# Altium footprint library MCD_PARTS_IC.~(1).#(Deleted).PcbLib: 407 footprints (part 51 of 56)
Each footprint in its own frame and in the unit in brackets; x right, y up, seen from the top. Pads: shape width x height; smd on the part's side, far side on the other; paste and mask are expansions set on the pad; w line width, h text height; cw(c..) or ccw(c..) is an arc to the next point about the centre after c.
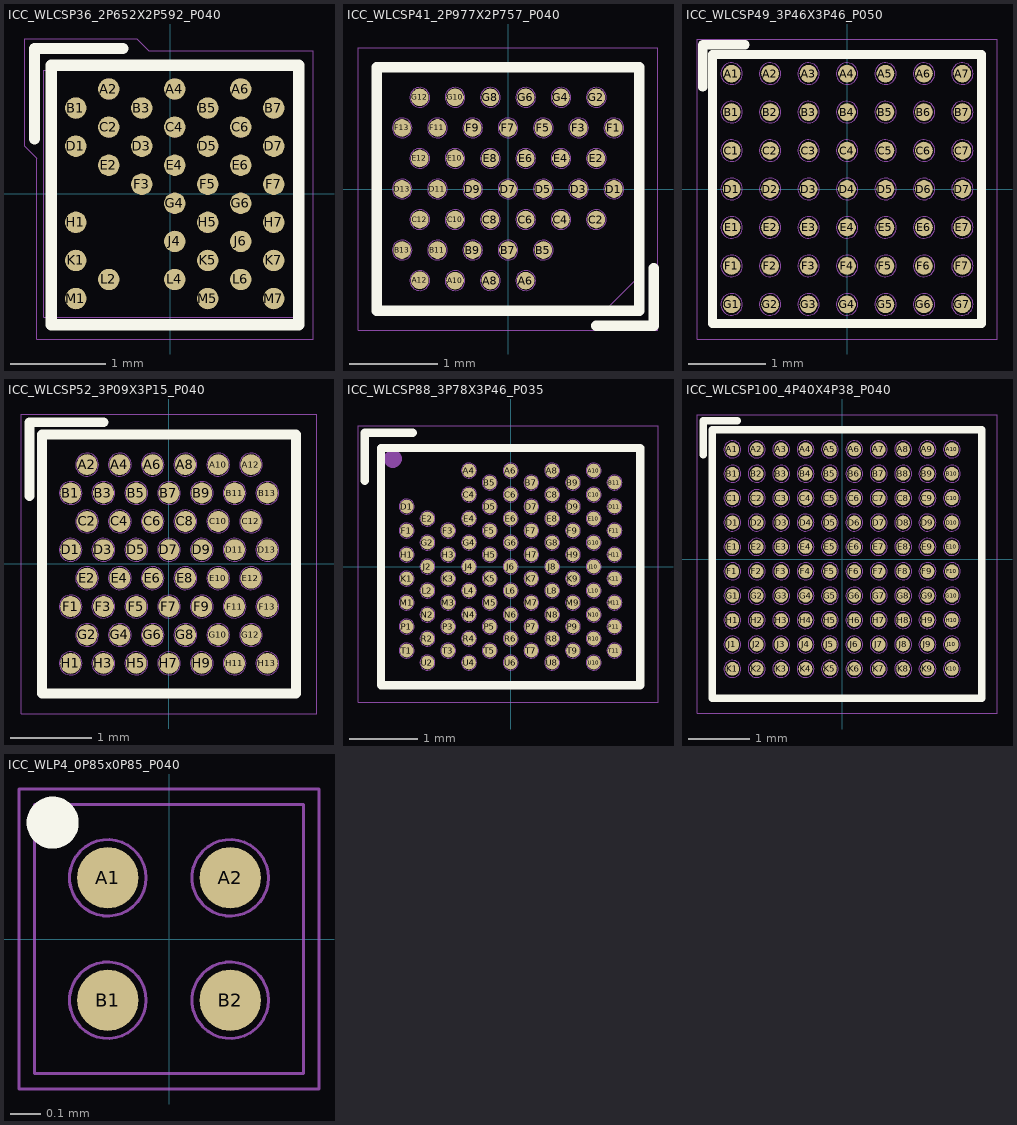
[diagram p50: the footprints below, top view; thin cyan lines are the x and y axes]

## ICC_WLCSP36_2P652X2P592_P040 [mm]
height 0.422
pads (36):
  round 0.225 smd paste+0.012 mask+0.032: A2(-0.644,1.1) A4(0.048,1.1) A6(0.741,1.1) B1(-0.991,0.9) B3(-0.298,0.9) B5(0.395,0.9) B7(1.088,0.9) C2(-0.644,0.7) C4(0.048,0.7) C6(0.741,0.7) D1(-0.991,0.5) D3(-0.298,0.5) D5(0.395,0.5) D7(1.088,0.5) E2(-0.644,0.3) E4(0.048,0.3) E6(0.741,0.3) F3(-0.298,0.1) F5(0.395,0.1) F7(1.088,0.1) G4(0.048,-0.1) G6(0.741,-0.1) H1(-0.991,-0.3) H5(0.395,-0.3) H7(1.088,-0.3) J4(0.048,-0.5) J6(0.741,-0.5) K1(-0.991,-0.7) K5(0.395,-0.7) K7(1.088,-0.7) L2(-0.644,-0.9) L4(0.048,-0.9) L6(0.741,-0.9) M1(-0.991,-1.1) M5(0.395,-1.1) M7(1.088,-1.1)
Top Overlay:
  lines w0.12: -1.425,0.575 -1.425,1.525 -0.5,1.525 ; -1.25,-1.375 1.35,-1.375 1.35,1.35 -1.25,1.35 -1.25,-1.375
M14-Top Assembly:
  circle w0.01: c-0.991,-1.1 r0.101
  circle w0.01: c0.395,-1.1 r0.101
  circle w0.01: c1.088,-1.1 r0.101
  circle w0.01: c-0.991,-0.7 r0.101
  circle w0.01: c0.395,-0.7 r0.101
  circle w0.01: c1.088,-0.7 r0.101
  circle w0.01: c-0.991,-0.3 r0.101
  circle w0.01: c0.395,-0.3 r0.101
  circle w0.01: c1.088,-0.3 r0.101
  circle w0.01: c-0.298,0.1 r0.101
  circle w0.01: c0.395,0.1 r0.101
  circle w0.01: c1.088,0.1 r0.101
  circle w0.01: c-0.991,0.5 r0.101
  circle w0.01: c-0.298,0.5 r0.101
  circle w0.01: c0.395,0.5 r0.101
  circle w0.01: c1.088,0.5 r0.101
  circle w0.01: c-0.991,0.9 r0.101
  circle w0.01: c-0.298,0.9 r0.101
  circle w0.01: c0.395,0.9 r0.101
  circle w0.01: c1.088,0.9 r0.101
  circle w0.01: c0.048,-0.1 r0.101
  circle w0.01: c0.741,-0.1 r0.101
  circle w0.01: c0.048,0.3 r0.101
  circle w0.01: c0.048,0.7 r0.101
  circle w0.01: c0.048,1.1 r0.101
  circle w0.01: c0.048,-0.5 r0.101
  circle w0.01: c0.048,-0.9 r0.101
  circle w0.01: c0.741,0.3 r0.101
  circle w0.01: c0.741,0.7 r0.101
  circle w0.01: c0.741,1.1 r0.101
  circle w0.01: c0.741,-0.5 r0.101
  circle w0.01: c0.741,-0.9 r0.101
  circle w0.01: c-0.644,1.1 r0.101
  circle w0.01: c-0.644,0.7 r0.101
  circle w0.01: c-0.644,0.3 r0.101
  circle w0.01: c-0.644,-0.9 r0.101
  lines w0.01: -1.326,-1.296 1.326,-1.296 1.326,1.296 -1.326,1.296 -1.326,-1.296
  text "'.Designator'" at -2,-0.5 h0.75
  text "A2" at -0.9,0.95 h0.5
M16-Top Courtyard:
  lines w0.01: -1.525,0.5 -1.4,0.375 -1.4,-1.525 1.5,-1.525 1.5,1.5 -0.225,1.5 -0.35,1.625 -1.525,1.625 -1.525,0.5
3D body: height 0.21, standoff 0.01, extent -1.092,-1.201 -0.89,-0.999
3D body: height 0.21, standoff 0.01, extent 0.294,-1.201 0.496,-0.999
3D body: height 0.21, standoff 0.01, extent 0.987,-1.201 1.189,-0.999
3D body: height 0.21, standoff 0.01, extent 0.64,-1.001 0.842,-0.799
3D body: height 0.21, standoff 0.01, extent -0.053,-1.001 0.149,-0.799
3D body: height 0.21, standoff 0.01, extent -0.746,-1.001 -0.543,-0.799
3D body: height 0.21, standoff 0.01, extent -1.092,-0.801 -0.89,-0.599
3D body: height 0.21, standoff 0.01, extent 0.294,-0.801 0.496,-0.599
3D body: height 0.21, standoff 0.01, extent 0.987,-0.801 1.189,-0.599
3D body: height 0.21, standoff 0.01, extent 0.64,-0.601 0.842,-0.399
3D body: height 0.21, standoff 0.01, extent -0.053,-0.601 0.149,-0.399
3D body: height 0.21, standoff 0.01, extent -1.092,-0.401 -0.89,-0.199
3D body: height 0.21, standoff 0.01, extent 0.294,-0.401 0.496,-0.199
3D body: height 0.21, standoff 0.01, extent 0.987,-0.401 1.189,-0.199
3D body: height 0.21, standoff 0.01, extent 0.64,-0.201 0.842,0.001
3D body: height 0.21, standoff 0.01, extent -0.053,-0.201 0.149,0.001
3D body: height 0.21, standoff 0.01, extent -0.399,-0.001 -0.197,0.201
3D body: height 0.21, standoff 0.01, extent 0.294,-0.001 0.496,0.201
3D body: height 0.21, standoff 0.01, extent 0.987,-0.001 1.189,0.201
3D body: height 0.21, standoff 0.01, extent 0.64,0.199 0.842,0.401
3D body: height 0.21, standoff 0.01, extent -0.053,0.199 0.149,0.401
3D body: height 0.21, standoff 0.01, extent -0.746,0.199 -0.543,0.401
3D body: height 0.42, standoff 0.17, extent -1.326,-1.296 1.326,1.296
3D body: height 0.21, standoff 0.01, extent -0.746,0.999 -0.543,1.201
3D body: height 0.43, standoff 0.42, extent -1.225,0.9 -0.925,1.2
3D body: height 0.21, standoff 0.01, extent -0.053,0.999 0.149,1.201
3D body: height 0.21, standoff 0.01, extent 0.64,0.999 0.842,1.201
3D body: height 0.21, standoff 0.01, extent 0.987,0.799 1.189,1.001
3D body: height 0.21, standoff 0.01, extent 0.294,0.799 0.496,1.001
3D body: height 0.21, standoff 0.01, extent -0.399,0.799 -0.197,1.001
3D body: height 0.21, standoff 0.01, extent -1.092,0.799 -0.89,1.001
3D body: height 0.21, standoff 0.01, extent -0.746,0.599 -0.543,0.801
3D body: height 0.21, standoff 0.01, extent -0.053,0.599 0.149,0.801
3D body: height 0.21, standoff 0.01, extent 0.64,0.599 0.842,0.801
3D body: height 0.21, standoff 0.01, extent 0.987,0.399 1.189,0.601
3D body: height 0.21, standoff 0.01, extent 0.294,0.399 0.496,0.601
3D body: height 0.21, standoff 0.01, extent -0.399,0.399 -0.197,0.601
3D body: height 0.21, standoff 0.01, extent -1.092,0.399 -0.89,0.601

## ICC_WLCSP41_2P977X2P757_P040 [mm] "MCD-03586"
height 0.49
pads (41):
  round 0.2 smd paste+0.025 mask+0.05: A6(0.2,-1.038) A8(-0.2,-1.038) A10(-0.6,-1.038) A12(-1,-1.034) B5(0.4,-0.692) B7(0,-0.692) B9(-0.4,-0.692) B11(-0.8,-0.692) B13(-1.2,-0.692) C2(1,-0.346) C4(0.6,-0.346) C6(0.2,-0.346) C8(-0.2,-0.346) C10(-0.6,-0.346) C12(-1,-0.346) D1(1.2,0) D3(0.8,0) D5(0.4,0) D7(0,0) D9(-0.4,0) D11(-0.8,0) D13(-1.2,0) E2(1,0.346) E4(0.6,0.346) E6(0.2,0.346) E8(-0.2,0.346) E10(-0.6,0.346) E12(-1,0.346) F1(1.2,0.692) F3(0.8,0.692) F5(0.4,0.692) F7(0,0.692) F9(-0.4,0.692) F11(-0.8,0.692) F13(-1.2,0.692) G2(1,1.038) G4(0.6,1.038) G6(0.2,1.038) G8(-0.2,1.038) G10(-0.6,1.038) G12(-1,1.038)
Top Overlay:
  lines w0.12: 1,-1.55 1.65,-1.55 1.65,-0.9 ; -1.488,-1.378 -1.488,1.379 1.489,1.379 1.489,-1.378 -1.488,-1.378
M14-Top Assembly:
  circle w0.01: c-0.6,1.038 r0.112
  circle w0.01: c0,0.692 r0.112
  circle w0.01: c-0.8,0.692 r0.112
  circle w0.01: c-1.2,0.692 r0.112
  circle w0.01: c-0.4,0.692 r0.112
  circle w0.01: c-0.2,0.346 r0.112
  circle w0.01: c-1,0.346 r0.112
  circle w0.01: c-0.6,0.346 r0.112
  circle w0.01: c-0.4,0 r0.112
  circle w0.01: c-1.2,0 r0.112
  circle w0.01: c1,1.038 r0.112
  circle w0.01: c0.6,1.038 r0.112
  circle w0.01: c1.2,0.692 r0.112
  circle w0.01: c0.8,0.692 r0.112
  circle w0.01: c0.4,0.692 r0.112
  circle w0.01: c1,0.346 r0.112
  circle w0.01: c0.2,0.346 r0.112
  circle w0.01: c1.2,0 r0.112
  circle w0.01: c0.8,0 r0.112
  circle w0.01: c0.4,0 r0.112
  circle w0.01: c1,-0.346 r0.112
  circle w0.01: c0.6,-0.346 r0.112
  circle w0.01: c0.4,-0.692 r0.112
  circle w0.01: c0.6,0.346 r0.112
  circle w0.01: c0.2,1.038 r0.112
  circle w0.01: c-0.2,1.038 r0.112
  circle w0.01: c-1,1.038 r0.112
  circle w0.01: c0,0 r0.112
  circle w0.01: c0.2,-0.346 r0.112
  circle w0.01: c-1,-0.346 r0.112
  circle w0.01: c-0.6,-0.346 r0.112
  circle w0.01: c-0.2,-0.346 r0.112
  circle w0.01: c-1.2,-0.692 r0.112
  circle w0.01: c-0.8,-0.692 r0.112
  circle w0.01: c0,-0.692 r0.112
  circle w0.01: c-0.4,-0.692 r0.112
  circle w0.01: c0.2,-1.038 r0.112
  circle w0.01: c-0.2,-1.038 r0.112
  circle w0.01: c-1,-1.038 r0.112
  circle w0.01: c-0.6,-1.038 r0.112
  circle w0.01: c-0.8,0 r0.112
  lines w0.01: -1.488,-1.378 1.489,-1.378 1.489,1.379 -1.488,1.379 -1.488,-1.378 ; 1.109,-1.368 1.489,-0.988 1.489,-1.368 1.109,-1.368
  text "'.Designator'" at -2,-0.5 h0.75
M16-Top Courtyard:
  lines w0.01: -1.7,-1.6 1.7,-1.6 1.7,1.6 -1.7,1.6 -1.7,-1.6
3D body: height 0.22, standoff -0.02, extent -0.12,-0.12 0.12,0.12
3D body: height 0.5, standoff 0.49, extent 1.05,-1.2 1.35,-0.9
3D body: height 0.22, standoff -0.02, extent -1.12,0.918 -0.88,1.158
3D body: height 0.22, standoff -0.02, extent -0.72,0.918 -0.48,1.158
3D body: height 0.22, standoff -0.02, extent -0.32,0.918 -0.08,1.158
3D body: height 0.22, standoff -0.02, extent 0.08,0.918 0.32,1.158
3D body: height 0.22, standoff -0.02, extent 0.48,0.918 0.72,1.158
3D body: height 0.22, standoff -0.02, extent 0.88,0.918 1.12,1.158
3D body: height 0.22, standoff -0.02, extent -1.32,0.572 -1.08,0.812
3D body: height 0.22, standoff -0.02, extent -0.92,0.572 -0.68,0.812
3D body: height 0.22, standoff -0.02, extent -0.52,0.572 -0.28,0.812
3D body: height 0.22, standoff -0.02, extent -0.12,0.572 0.12,0.812
3D body: height 0.22, standoff -0.02, extent 0.28,0.572 0.52,0.812
3D body: height 0.22, standoff -0.02, extent 0.68,0.572 0.92,0.812
3D body: height 0.22, standoff -0.02, extent 1.08,0.572 1.32,0.812
3D body: height 0.22, standoff -0.02, extent -1.12,0.226 -0.88,0.466
3D body: height 0.22, standoff -0.02, extent -0.72,0.226 -0.48,0.466
3D body: height 0.22, standoff -0.02, extent -0.32,0.226 -0.08,0.466
3D body: height 0.22, standoff -0.02, extent 0.08,0.226 0.32,0.466
3D body: height 0.22, standoff -0.02, extent 0.48,0.226 0.72,0.466
3D body: height 0.22, standoff -0.02, extent 0.88,0.226 1.12,0.466
3D body: height 0.22, standoff -0.02, extent -1.32,-0.12 -1.08,0.12
3D body: height 0.22, standoff -0.02, extent -0.92,-0.12 -0.68,0.12
3D body: height 0.22, standoff -0.02, extent -0.52,-0.12 -0.28,0.12
3D body: height 0.22, standoff -0.02, extent 0.28,-0.12 0.52,0.12
3D body: height 0.22, standoff -0.02, extent 0.68,-0.12 0.92,0.12
3D body: height 0.22, standoff -0.02, extent 1.08,-0.12 1.32,0.12
3D body: height 0.22, standoff -0.02, extent -1.12,-0.466 -0.88,-0.226
3D body: height 0.22, standoff -0.02, extent -0.72,-0.466 -0.48,-0.226
3D body: height 0.22, standoff -0.02, extent -0.32,-0.466 -0.08,-0.226
3D body: height 0.22, standoff -0.02, extent 0.08,-0.466 0.32,-0.226
3D body: height 0.22, standoff -0.02, extent 0.48,-0.466 0.72,-0.226
3D body: height 0.22, standoff -0.02, extent 0.88,-0.466 1.12,-0.226
3D body: height 0.22, standoff -0.02, extent -1.32,-0.812 -1.08,-0.572
3D body: height 0.22, standoff -0.02, extent -0.92,-0.812 -0.68,-0.572
3D body: height 0.22, standoff -0.02, extent -0.52,-0.812 -0.28,-0.572
3D body: height 0.22, standoff -0.02, extent -0.12,-0.812 0.12,-0.572
3D body: height 0.22, standoff -0.02, extent 0.28,-0.812 0.52,-0.572
3D body: height 0.22, standoff -0.02, extent -1.12,-1.154 -0.88,-0.914
3D body: height 0.22, standoff -0.02, extent -0.72,-1.158 -0.48,-0.918
3D body: height 0.22, standoff -0.02, extent -0.32,-1.158 -0.08,-0.918
3D body: height 0.22, standoff -0.02, extent 0.08,-1.158 0.32,-0.918
3D body: height 0.49, standoff 0.18, extent -1.488,-1.378 1.489,1.379

## ICC_WLCSP49_3P46X3P46_P050 [mm] "MCD-02315"
height 0.66
pads (49):
  round 0.23 smd paste+0.025 mask+0.05: A1(-1.5,1.5) A2(-1,1.5) A3(-0.5,1.5) A4(0,1.5) A5(0.5,1.5) A6(1,1.5) A7(1.5,1.5) B1(-1.5,1) B2(-1,1) B3(-0.5,1) B4(0,1) B5(0.5,1) B6(1,1) B7(1.5,1) C1(-1.5,0.5) C2(-1,0.5) C3(-0.5,0.5) C4(0,0.5) C5(0.5,0.5) C6(1,0.5) C7(1.5,0.5) D1(-1.5,0) D2(-1,0) D3(-0.5,0) D4(0,0) D5(0.5,0) D6(1,0) D7(1.5,0) E1(-1.5,-0.5) E2(-1,-0.5) E3(-0.5,-0.5) E4(0,-0.5) E5(0.5,-0.5) E6(1,-0.5) E7(1.5,-0.5) F1(-1.5,-1) F2(-1,-1) F3(-0.5,-1) F4(0,-1) F5(0.5,-1) F6(1,-1) F7(1.5,-1) G1(-1.5,-1.5) G2(-1,-1.5) G3(-0.5,-1.5) G4(0,-1.5) G5(0.5,-1.5) G6(1,-1.5) G7(1.5,-1.5)
Top Overlay:
  lines w0.12: -1.875,1.325 -1.875,1.875 -1.325,1.875 ; -1.75,-1.75 1.75,-1.75 1.75,1.75 -1.75,1.75 -1.75,-1.75
M14-Top Assembly:
  circle w0.01: c1.5,-1.5 r0.14
  circle w0.01: c1,-1.5 r0.14
  circle w0.01: c0.5,-1.5 r0.14
  circle w0.01: c0,-1.5 r0.14
  circle w0.01: c-0.5,-1.5 r0.14
  circle w0.01: c-1,-1.5 r0.14
  circle w0.01: c-1.5,-1.5 r0.14
  circle w0.01: c1.5,-1 r0.14
  circle w0.01: c1,-1 r0.14
  circle w0.01: c0.5,-1 r0.14
  circle w0.01: c0,-1 r0.14
  circle w0.01: c-0.5,-1 r0.14
  circle w0.01: c-1,-1 r0.14
  circle w0.01: c-1.5,-1 r0.14
  circle w0.01: c1.5,-0.5 r0.14
  circle w0.01: c1,-0.5 r0.14
  circle w0.01: c0.5,-0.5 r0.14
  circle w0.01: c0,-0.5 r0.14
  circle w0.01: c-0.5,-0.5 r0.14
  circle w0.01: c-1,-0.5 r0.14
  circle w0.01: c-1.5,-0.5 r0.14
  circle w0.01: c1.5,0 r0.14
  circle w0.01: c1,0 r0.14
  circle w0.01: c0.5,0 r0.14
  circle w0.01: c0,0 r0.14
  circle w0.01: c-0.5,0 r0.14
  circle w0.01: c-1,0 r0.14
  circle w0.01: c-1.5,0 r0.14
  circle w0.01: c1.5,0.5 r0.14
  circle w0.01: c1,0.5 r0.14
  circle w0.01: c0.5,0.5 r0.14
  circle w0.01: c0,0.5 r0.14
  circle w0.01: c-0.5,0.5 r0.14
  circle w0.01: c-1,0.5 r0.14
  circle w0.01: c-1.5,0.5 r0.14
  circle w0.01: c1.5,1 r0.14
  circle w0.01: c1,1 r0.14
  circle w0.01: c0.5,1 r0.14
  circle w0.01: c0,1 r0.14
  circle w0.01: c-0.5,1 r0.14
  circle w0.01: c-1,1 r0.14
  circle w0.01: c-1.5,1 r0.14
  circle w0.01: c1.5,1.5 r0.14
  circle w0.01: c1,1.5 r0.14
  circle w0.01: c0.5,1.5 r0.14
  circle w0.01: c0,1.5 r0.14
  circle w0.01: c-0.5,1.5 r0.14
  circle w0.01: c-1,1.5 r0.14
  circle w0.01: c-1.5,1.5 r0.14
  lines w0.01: -1.75,-1.75 1.75,-1.75 1.75,1.75 -1.75,1.75 -1.75,-1.75
  text "A1" at -1.725,1.35 h0.5
  text "'.Designator'" at -2,-0.5 h0.75
M16-Top Courtyard:
  lines w0.01: -1.95,-1.95 1.95,-1.95 1.95,1.95 -1.95,1.95 -1.95,-1.95
3D body: height 0.32, standoff -0.04, extent 1.329,-1.677 1.68,-1.323
3D body: height 0.32, standoff -0.04, extent 0.829,-1.677 1.18,-1.323
3D body: height 0.32, standoff -0.04, extent 0.329,-1.677 0.68,-1.323
3D body: height 0.32, standoff -0.04, extent -0.171,-1.677 0.18,-1.323
3D body: height 0.32, standoff -0.04, extent -0.671,-1.677 -0.32,-1.323
3D body: height 0.32, standoff -0.04, extent -1.171,-1.677 -0.82,-1.323
3D body: height 0.32, standoff -0.04, extent -1.671,-1.677 -1.32,-1.323
3D body: height 0.32, standoff -0.04, extent 1.329,-1.177 1.68,-0.823
3D body: height 0.32, standoff -0.04, extent 0.829,-1.177 1.18,-0.823
3D body: height 0.32, standoff -0.04, extent 0.329,-1.177 0.68,-0.823
3D body: height 0.32, standoff -0.04, extent -0.171,-1.177 0.18,-0.823
3D body: height 0.32, standoff -0.04, extent -0.671,-1.177 -0.32,-0.823
3D body: height 0.32, standoff -0.04, extent -1.171,-1.177 -0.82,-0.823
3D body: height 0.32, standoff -0.04, extent -1.671,-1.177 -1.32,-0.823
3D body: height 0.32, standoff -0.04, extent 1.329,-0.677 1.68,-0.323
3D body: height 0.32, standoff -0.04, extent 0.829,-0.677 1.18,-0.323
3D body: height 0.32, standoff -0.04, extent 0.329,-0.677 0.68,-0.323
3D body: height 0.32, standoff -0.04, extent -0.171,-0.677 0.18,-0.323
3D body: height 0.32, standoff -0.04, extent -0.671,-0.677 -0.32,-0.323
3D body: height 0.32, standoff -0.04, extent -1.171,-0.677 -0.82,-0.323
3D body: height 0.32, standoff -0.04, extent -1.671,-0.677 -1.32,-0.323
3D body: height 0.32, standoff -0.04, extent 1.329,-0.177 1.68,0.177
3D body: height 0.32, standoff -0.04, extent 0.829,-0.177 1.18,0.177
3D body: height 0.32, standoff -0.04, extent 0.329,-0.177 0.68,0.177
3D body: height 0.32, standoff -0.04, extent -0.171,-0.177 0.18,0.177
3D body: height 0.32, standoff -0.04, extent -0.671,-0.177 -0.32,0.177
3D body: height 0.32, standoff -0.04, extent -1.171,-0.177 -0.82,0.177
3D body: height 0.32, standoff -0.04, extent -1.671,-0.177 -1.32,0.177
3D body: height 0.32, standoff -0.04, extent 1.329,0.323 1.68,0.677
3D body: height 0.32, standoff -0.04, extent 0.829,0.323 1.18,0.677
3D body: height 0.32, standoff -0.04, extent 0.329,0.323 0.68,0.677
3D body: height 0.32, standoff -0.04, extent -0.171,0.323 0.18,0.677
3D body: height 0.32, standoff -0.04, extent -0.671,0.323 -0.32,0.677
3D body: height 0.32, standoff -0.04, extent -1.171,0.323 -0.82,0.677
3D body: height 0.32, standoff -0.04, extent -1.671,0.323 -1.32,0.677
3D body: height 0.32, standoff -0.04, extent 1.329,0.823 1.68,1.177
3D body: height 0.32, standoff -0.04, extent 0.829,0.823 1.18,1.177
3D body: height 0.32, standoff -0.04, extent 0.329,0.823 0.68,1.177
3D body: height 0.32, standoff -0.04, extent -0.171,0.823 0.18,1.177
3D body: height 0.32, standoff -0.04, extent -0.671,0.823 -0.32,1.177
3D body: height 0.32, standoff -0.04, extent -1.171,0.823 -0.82,1.177
3D body: height 0.32, standoff -0.04, extent -1.671,0.823 -1.32,1.177
3D body: height 0.32, standoff -0.04, extent 1.329,1.323 1.68,1.677
3D body: height 0.32, standoff -0.04, extent 0.829,1.323 1.18,1.677
3D body: height 0.32, standoff -0.04, extent 0.329,1.323 0.68,1.677
3D body: height 0.32, standoff -0.04, extent -0.171,1.323 0.18,1.677
3D body: height 0.32, standoff -0.04, extent -0.671,1.323 -0.32,1.677
3D body: height 0.32, standoff -0.04, extent -1.171,1.323 -0.82,1.677
3D body: height 0.32, standoff -0.04, extent -1.671,1.323 -1.32,1.677
3D body: height 0.66, standoff 0.24, extent -1.75,-1.75 1.75,1.75
3D body: height 0.67, standoff 0.66, extent -1.575,1.225 -1.216,1.584

## ICC_WLCSP52_3P09X3P15_P040 [mm] "MCD-02341"
height 0.58
pads (52):
  round 0.255 smd paste+0.017 mask+0.035: A2(-1,1.212) A4(-0.6,1.212) A6(-0.2,1.212) A8(0.2,1.212) A10(0.6,1.212) A12(1,1.212) B1(-1.2,0.866) B3(-0.8,0.866) B5(-0.4,0.866) B7(0,0.866) B9(0.4,0.866) B11(0.8,0.866) B13(1.2,0.866) C2(-1,0.52) C4(-0.6,0.52) C6(-0.2,0.52) C8(0.2,0.52) C10(0.6,0.52) C12(1,0.52) D1(-1.2,0.173) D3(-0.8,0.173) D5(-0.4,0.173) D7(0,0.173) D9(0.4,0.173) D11(0.8,0.173) D13(1.2,0.173) E2(-1,-0.173) E4(-0.6,-0.173) E6(-0.2,-0.173) E8(0.2,-0.173) E10(0.6,-0.173) E12(1,-0.173) F1(-1.2,-0.52) F3(-0.8,-0.52) F5(-0.4,-0.52) F7(0,-0.52) F9(0.4,-0.52) F11(0.8,-0.52) F13(1.2,-0.52) G2(-1,-0.866) G4(-0.6,-0.866) G6(-0.2,-0.866) G8(0.2,-0.866) G10(0.6,-0.866) G12(1,-0.866) H1(-1.2,-1.212) H3(-0.8,-1.212) H5(-0.4,-1.212) H7(0,-1.212) H9(0.4,-1.212) H11(0.8,-1.212) H13(1.2,-1.212)
Top Overlay:
  lines w0.12: -1.7,0.83 -1.7,1.73 -0.8,1.73 ; -1.55,-1.58 -1.55,1.58 1.55,1.58 1.55,-1.58 -1.55,-1.58
M14-Top Assembly:
  circle w0.01: c1.2,-1.212 r0.14
  circle w0.01: c0.8,-1.212 r0.14
  circle w0.01: c0.4,-1.212 r0.14
  circle w0.01: c0,-1.212 r0.14
  circle w0.01: c-0.4,-1.212 r0.14
  circle w0.01: c-0.8,-1.212 r0.14
  circle w0.01: c-1.2,-1.212 r0.14
  circle w0.01: c1,-0.866 r0.14
  circle w0.01: c0.6,-0.866 r0.14
  circle w0.01: c0.2,-0.866 r0.14
  circle w0.01: c-0.2,-0.866 r0.14
  circle w0.01: c-0.6,-0.866 r0.14
  circle w0.01: c-1,-0.866 r0.14
  circle w0.01: c1.2,-0.52 r0.14
  circle w0.01: c0.8,-0.52 r0.14
  circle w0.01: c0.4,-0.52 r0.14
  circle w0.01: c0,-0.52 r0.14
  circle w0.01: c-0.4,-0.52 r0.14
  circle w0.01: c-0.8,-0.52 r0.14
  circle w0.01: c-1.2,-0.52 r0.14
  circle w0.01: c1,-0.173 r0.14
  circle w0.01: c0.6,-0.173 r0.14
  circle w0.01: c0.2,-0.173 r0.14
  circle w0.01: c-0.2,-0.173 r0.14
  circle w0.01: c-0.6,-0.173 r0.14
  circle w0.01: c-1,-0.173 r0.14
  circle w0.01: c1.2,0.173 r0.14
  circle w0.01: c0.8,0.173 r0.14
  circle w0.01: c0.4,0.173 r0.14
  circle w0.01: c0,0.173 r0.14
  circle w0.01: c-0.4,0.173 r0.14
  circle w0.01: c-0.8,0.173 r0.14
  circle w0.01: c-1.2,0.173 r0.14
  circle w0.01: c1,0.52 r0.14
  circle w0.01: c0.6,0.52 r0.14
  circle w0.01: c0.2,0.52 r0.14
  circle w0.01: c-0.2,0.52 r0.14
  circle w0.01: c-0.6,0.52 r0.14
  circle w0.01: c-1,0.52 r0.14
  circle w0.01: c1.2,0.866 r0.14
  circle w0.01: c0.8,0.866 r0.14
  circle w0.01: c0.4,0.866 r0.14
  circle w0.01: c0,0.866 r0.14
  circle w0.01: c-0.4,0.866 r0.14
  circle w0.01: c-0.8,0.866 r0.14
  circle w0.01: c-1.2,0.866 r0.14
  circle w0.01: c1,1.212 r0.14
  circle w0.01: c0.6,1.212 r0.14
  circle w0.01: c0.2,1.212 r0.14
  circle w0.01: c-0.2,1.212 r0.14
  circle w0.01: c-0.6,1.212 r0.14
  circle w0.01: c-1,1.212 r0.14
  lines w0.01: -1.55,-1.58 -1.55,1.58 1.55,1.58 1.55,-1.58 -1.55,-1.58
  text "'.Designator'" at -2,-0.5 h0.75
  text "A2" at -1.275,1.063 h0.5
  text "H13" at 0.775,-1.363 h0.5
  text "H1" at -1.425,-1.375 h0.5
  text "A12" at 0.614,1.053 h0.5
M16-Top Courtyard:
  lines w0.01: -1.8,-1.83 -1.8,1.83 1.8,1.83 1.8,-1.83 -1.8,-1.83
3D body: height 0.26, standoff -0.02, extent 1.069,-1.35 1.34,-1.074
3D body: height 0.26, standoff -0.02, extent 0.669,-1.35 0.94,-1.074
3D body: height 0.26, standoff -0.02, extent 0.269,-1.35 0.54,-1.074
3D body: height 0.26, standoff -0.02, extent -0.131,-1.35 0.14,-1.074
3D body: height 0.26, standoff -0.02, extent -0.531,-1.35 -0.26,-1.074
3D body: height 0.26, standoff -0.02, extent -0.931,-1.35 -0.66,-1.074
3D body: height 0.26, standoff -0.02, extent -1.331,-1.35 -1.06,-1.074
3D body: height 0.26, standoff -0.02, extent 0.869,-1.004 1.14,-0.728
3D body: height 0.26, standoff -0.02, extent 0.469,-1.004 0.74,-0.728
3D body: height 0.26, standoff -0.02, extent 0.069,-1.004 0.34,-0.728
3D body: height 0.26, standoff -0.02, extent -0.331,-1.004 -0.06,-0.728
3D body: height 0.26, standoff -0.02, extent -0.731,-1.004 -0.46,-0.728
3D body: height 0.26, standoff -0.02, extent -1.131,-1.004 -0.86,-0.728
3D body: height 0.26, standoff -0.02, extent 1.069,-0.657 1.34,-0.382
3D body: height 0.26, standoff -0.02, extent 0.669,-0.657 0.94,-0.382
3D body: height 0.26, standoff -0.02, extent 0.269,-0.657 0.54,-0.382
3D body: height 0.26, standoff -0.02, extent -0.131,-0.657 0.14,-0.382
3D body: height 0.26, standoff -0.02, extent -0.531,-0.657 -0.26,-0.382
3D body: height 0.26, standoff -0.02, extent -0.931,-0.657 -0.66,-0.382
3D body: height 0.26, standoff -0.02, extent -1.331,-0.657 -1.06,-0.382
3D body: height 0.26, standoff -0.02, extent 0.869,-0.311 1.14,-0.035
3D body: height 0.26, standoff -0.02, extent 0.469,-0.311 0.74,-0.035
3D body: height 0.26, standoff -0.02, extent 0.069,-0.311 0.34,-0.035
3D body: height 0.26, standoff -0.02, extent -0.331,-0.311 -0.06,-0.035
3D body: height 0.26, standoff -0.02, extent -0.731,-0.311 -0.46,-0.035
3D body: height 0.26, standoff -0.02, extent -1.131,-0.311 -0.86,-0.035
3D body: height 0.26, standoff -0.02, extent 1.069,0.036 1.34,0.311
3D body: height 0.26, standoff -0.02, extent 0.669,0.036 0.94,0.311
3D body: height 0.26, standoff -0.02, extent 0.269,0.036 0.54,0.311
3D body: height 0.26, standoff -0.02, extent -0.131,0.036 0.14,0.311
3D body: height 0.26, standoff -0.02, extent -0.531,0.036 -0.26,0.311
3D body: height 0.26, standoff -0.02, extent -0.931,0.036 -0.66,0.311
3D body: height 0.26, standoff -0.02, extent -1.331,0.036 -1.06,0.311
3D body: height 0.26, standoff -0.02, extent 0.869,0.382 1.14,0.658
3D body: height 0.26, standoff -0.02, extent 0.469,0.382 0.74,0.658
3D body: height 0.26, standoff -0.02, extent 0.069,0.382 0.34,0.658
3D body: height 0.26, standoff -0.02, extent -0.331,0.382 -0.06,0.658
3D body: height 0.26, standoff -0.02, extent -0.731,0.382 -0.46,0.658
3D body: height 0.26, standoff -0.02, extent -1.131,0.382 -0.86,0.658
3D body: height 0.26, standoff -0.02, extent 1.069,0.728 1.34,1.004
3D body: height 0.26, standoff -0.02, extent 0.669,0.728 0.94,1.004
3D body: height 0.26, standoff -0.02, extent 0.269,0.728 0.54,1.004
3D body: height 0.26, standoff -0.02, extent -0.131,0.728 0.14,1.004
3D body: height 0.26, standoff -0.02, extent -0.531,0.728 -0.26,1.004
3D body: height 0.26, standoff -0.02, extent -0.931,0.728 -0.66,1.004
3D body: height 0.26, standoff -0.02, extent -1.331,0.728 -1.06,1.004
3D body: height 0.26, standoff -0.02, extent 0.869,1.075 1.14,1.35
3D body: height 0.26, standoff -0.02, extent 0.469,1.075 0.74,1.35
3D body: height 0.26, standoff -0.02, extent 0.069,1.075 0.34,1.35
3D body: height 0.26, standoff -0.02, extent -0.331,1.075 -0.06,1.35
3D body: height 0.26, standoff -0.02, extent -0.731,1.075 -0.46,1.35
3D body: height 0.26, standoff -0.02, extent -1.131,1.075 -0.86,1.35
3D body: height 0.59, standoff 0.58, extent -1.399,1.13 -1.1,1.43
3D body: height 0.58, standoff 0.19, extent -1.55,-1.58 1.55,1.58

## ICC_WLCSP88_3P78X3P46_P035 [mm] "MCD-03958"
height 0.5
pads (88):
  round 0.2 smd paste+0 mask+0.038: A4(-0.606,1.4) A6(0,1.4) A8(0.606,1.4) A10(1.212,1.4) B5(-0.303,1.225) B7(0.303,1.225) B9(0.909,1.225) B11(1.516,1.225) C4(-0.606,1.05) C6(0,1.05) C8(0.606,1.05) C10(1.212,1.05) D1(-1.516,0.875) D5(-0.303,0.875) D7(0.303,0.875) D9(0.909,0.875) D11(1.516,0.875) E2(-1.212,0.7) E4(-0.606,0.7) E6(0,0.7) E8(0.606,0.7) E10(1.212,0.7) F1(-1.516,0.525) F3(-0.909,0.525) F5(-0.303,0.525) F7(0.303,0.525) F9(0.909,0.525) F11(1.516,0.525) G2(-1.212,0.35) G4(-0.606,0.35) G6(0,0.35) G8(0.606,0.35) G10(1.212,0.35) H1(-1.516,0.175) H3(-0.909,0.175) H5(-0.303,0.175) H7(0.303,0.175) H9(0.909,0.175) H11(1.516,0.175) J2(-1.212,0) J4(-0.606,0) J6(0,0) J8(0.606,0) J10(1.212,0) K1(-1.516,-0.175) K3(-0.909,-0.175) K5(-0.303,-0.175) K7(0.303,-0.175) K9(0.909,-0.175) K11(1.516,-0.175) L2(-1.212,-0.35) L4(-0.606,-0.35) L6(0,-0.35) L8(0.606,-0.35) L10(1.212,-0.35) M1(-1.516,-0.525) M3(-0.909,-0.525) M5(-0.303,-0.525) M7(0.303,-0.525) M9(0.909,-0.525) M11(1.516,-0.525) N2(-1.212,-0.7) N4(-0.606,-0.7) N6(0,-0.7) N8(0.606,-0.7) N10(1.212,-0.7) P1(-1.516,-0.875) P3(-0.909,-0.875) P5(-0.303,-0.875) P7(0.303,-0.875) P9(0.909,-0.875) P11(1.516,-0.875) R2(-1.212,-1.05) R4(-0.606,-1.05) R6(0,-1.05) R8(0.606,-1.05) R10(1.212,-1.05) T1(-1.516,-1.225) T3(-0.909,-1.225) T5(-0.303,-1.225) T7(0.303,-1.225) T9(0.909,-1.225) T11(1.516,-1.225) U2(-1.212,-1.4) U4(-0.606,-1.4) U6(0,-1.4) U8(0.606,-1.4) U10(1.212,-1.4)
Top Overlay:
  lines w0.12: -2.125,1.25 -2.125,1.95 -1.425,1.95 ; -1.89,-1.73 -1.89,1.73 1.89,1.73 1.89,-1.73 -1.89,-1.73
M14-Top Assembly:
  circle w0.254: c-1.718,1.572 r0.004
  circle w0.01: c-0.606,-0.35 r0.11
  circle w0.01: c-0.909,0.525 r0.11
  circle w0.01: c-0.909,0.175 r0.11
  circle w0.01: c-0.909,-0.175 r0.11
  circle w0.01: c-1.212,0.7 r0.11
  circle w0.01: c-1.212,0.35 r0.11
  circle w0.01: c-1.212,0 r0.11
  circle w0.01: c-1.212,-0.35 r0.11
  circle w0.01: c-1.516,0.525 r0.11
  circle w0.01: c-1.516,0.875 r0.11
  circle w0.01: c-1.516,0.175 r0.11
  circle w0.01: c-1.516,-0.175 r0.11
  circle w0.01: c-0.909,-0.525 r0.11
  circle w0.01: c1.516,0.525 r0.11
  circle w0.01: c1.516,1.225 r0.11
  circle w0.01: c1.516,0.875 r0.11
  circle w0.01: c1.516,0.175 r0.11
  circle w0.01: c1.516,-0.175 r0.11
  circle w0.01: c1.212,0.7 r0.11
  circle w0.01: c1.212,0.35 r0.11
  circle w0.01: c1.212,1.4 r0.11
  circle w0.01: c1.212,1.05 r0.11
  circle w0.01: c1.212,0 r0.11
  circle w0.01: c1.212,-0.35 r0.11
  circle w0.01: c0.909,0.525 r0.11
  circle w0.01: c0.909,1.225 r0.11
  circle w0.01: c0.909,0.875 r0.11
  circle w0.01: c0.909,0.175 r0.11
  circle w0.01: c0.909,-0.175 r0.11
  circle w0.01: c0.606,0.35 r0.11
  circle w0.01: c0.606,0.7 r0.11
  circle w0.01: c0.606,1.05 r0.11
  circle w0.01: c0.606,1.4 r0.11
  circle w0.01: c0.606,0 r0.11
  circle w0.01: c0.303,0.525 r0.11
  circle w0.01: c0.303,1.225 r0.11
  circle w0.01: c0.303,0.875 r0.11
  circle w0.01: c0.303,0.175 r0.11
  circle w0.01: c0.303,-0.175 r0.11
  circle w0.01: c0.606,-0.35 r0.11
  circle w0.01: c1.516,-0.525 r0.11
  circle w0.01: c0.909,-0.525 r0.11
  circle w0.01: c0.303,-0.525 r0.11
  circle w0.01: c0.606,-0.7 r0.11
  circle w0.01: c1.212,-0.7 r0.11
  circle w0.01: c0.909,-0.875 r0.11
  circle w0.01: c1.516,-0.875 r0.11
  circle w0.01: c0.303,-0.875 r0.11
  circle w0.01: c0.606,-1.05 r0.11
  circle w0.01: c1.212,-1.05 r0.11
  circle w0.01: c0.909,-1.225 r0.11
  circle w0.01: c0.303,-1.225 r0.11
  circle w0.01: c1.516,-1.225 r0.11
  circle w0.01: c1.212,-1.4 r0.11
  circle w0.01: c0.606,-1.4 r0.11
  circle w0.01: c0,0.7 r0.11
  circle w0.01: c0,1.4 r0.11
  circle w0.01: c0,0.35 r0.11
  circle w0.01: c0,0 r0.11
  circle w0.01: c0,-0.35 r0.11
  circle w0.01: c0,1.05 r0.11
  circle w0.01: c-0.303,0.875 r0.11
  circle w0.01: c-0.303,1.225 r0.11
  circle w0.01: c-0.303,0.525 r0.11
  circle w0.01: c-0.303,0.175 r0.11
  circle w0.01: c-0.303,-0.175 r0.11
  circle w0.01: c-0.303,-0.525 r0.11
  circle w0.01: c-0.606,1.4 r0.11
  circle w0.01: c-0.606,1.05 r0.11
  circle w0.01: c-0.606,0.7 r0.11
  circle w0.01: c-0.606,0.35 r0.11
  circle w0.01: c-0.606,0 r0.11
  circle w0.01: c-1.516,-0.525 r0.11
  circle w0.01: c0,-0.7 r0.11
  circle w0.01: c-1.212,-0.7 r0.11
  circle w0.01: c-0.606,-0.7 r0.11
  circle w0.01: c-1.516,-0.875 r0.11
  circle w0.01: c-0.303,-0.875 r0.11
  circle w0.01: c-0.909,-0.875 r0.11
  circle w0.01: c0,-1.05 r0.11
  circle w0.01: c-0.606,-1.05 r0.11
  circle w0.01: c-1.212,-1.05 r0.11
  circle w0.01: c-1.516,-1.225 r0.11
  circle w0.01: c-0.303,-1.225 r0.11
  circle w0.01: c-0.909,-1.225 r0.11
  circle w0.01: c0,-1.4 r0.11
  circle w0.01: c-0.606,-1.4 r0.11
  circle w0.01: c-1.212,-1.4 r0.11
  lines w0.01: -1.89,-1.73 1.89,-1.73 1.89,1.73 -1.89,1.73 -1.89,-1.73
  text "'.Designator'" at -2,-0.5 h0.75
M16-Top Courtyard:
  lines w0.01: -2.225,-1.975 2.15,-1.975 2.15,2.05 -2.225,2.05 -2.225,-1.975
3D body: height 0.25, standoff 0, extent 1.391,0.4 1.641,0.65
3D body: height 0.25, standoff 0, extent 1.391,-0.3 1.641,-0.05
3D body: height 0.25, standoff 0, extent 1.391,0.05 1.641,0.3
3D body: height 0.25, standoff 0, extent 1.391,1.1 1.641,1.35
3D body: height 0.25, standoff 0, extent 1.391,0.75 1.641,1
3D body: height 0.25, standoff 0, extent 1.088,0.575 1.338,0.825
3D body: height 0.25, standoff 0, extent 1.088,0.225 1.338,0.475
3D body: height 0.25, standoff 0, extent 1.088,1.275 1.338,1.525
3D body: height 0.25, standoff 0, extent 1.087,0.925 1.337,1.175
3D body: height 0.25, standoff 0, extent 1.073,-0.113 1.323,0.137
3D body: height 0.25, standoff 0, extent 0.784,0.75 1.034,1
3D body: height 0.25, standoff 0, extent 0.784,0.4 1.034,0.65
3D body: height 0.25, standoff 0, extent 0.784,0.05 1.034,0.3
3D body: height 0.25, standoff 0, extent 0.784,1.1 1.034,1.35
3D body: height 0.25, standoff 0, extent 0.784,-0.3 1.034,-0.05
3D body: height 0.25, standoff 0, extent 0.481,-0.125 0.731,0.125
3D body: height 0.25, standoff 0, extent 0.481,0.925 0.731,1.175
3D body: height 0.25, standoff 0, extent 0.481,0.575 0.731,0.825
3D body: height 0.25, standoff 0, extent 0.481,0.225 0.731,0.475
3D body: height 0.25, standoff 0, extent 0.481,-0.475 0.731,-0.225
3D body: height 0.25, standoff 0, extent 0.481,1.275 0.731,1.525
3D body: height 0.25, standoff 0, extent 0.178,0.4 0.428,0.65
3D body: height 0.25, standoff 0, extent 0.178,0.05 0.428,0.3
3D body: height 0.25, standoff 0, extent 0.178,-0.3 0.428,-0.05
3D body: height 0.25, standoff 0, extent 0.178,0.75 0.428,1
3D body: height 0.25, standoff 0, extent 1.088,-0.475 1.338,-0.225
3D body: height 0.25, standoff 0, extent 0.481,-1.175 0.731,-0.925
3D body: height 0.25, standoff 0, extent 1.391,-1 1.641,-0.75
3D body: height 0.25, standoff 0, extent 1.088,-0.825 1.338,-0.575
3D body: height 0.25, standoff 0, extent 0.784,-0.65 1.034,-0.4
3D body: height 0.25, standoff 0, extent 0.475,-0.829 0.725,-0.579
3D body: height 0.25, standoff 0, extent 0.184,-0.642 0.434,-0.392
3D body: height 0.25, standoff 0, extent 1.088,-1.175 1.338,-0.925
3D body: height 0.25, standoff 0, extent 0.784,-1 1.034,-0.75
3D body: height 0.25, standoff 0, extent 1.391,-0.65 1.641,-0.4
3D body: height 0.25, standoff 0, extent 0.178,-1 0.428,-0.75
3D body: height 0.25, standoff 0, extent 1.391,-1.35 1.641,-1.1
3D body: height 0.25, standoff 0, extent 0.784,-1.35 1.034,-1.1
3D body: height 0.25, standoff 0, extent 0.178,-1.35 0.428,-1.1
3D body: height 0.25, standoff 0, extent 0.481,-1.525 0.731,-1.275
3D body: height 0.25, standoff 0, extent 1.073,-1.525 1.323,-1.275
3D body: height 0.25, standoff 0, extent 0.178,1.1 0.428,1.35
3D body: height 0.25, standoff 0, extent -0.125,0.575 0.125,0.825
3D body: height 0.25, standoff 0, extent -0.125,0.925 0.125,1.175
3D body: height 0.25, standoff 0, extent -0.125,1.275 0.125,1.525
3D body: height 0.25, standoff 0, extent -0.125,0.225 0.125,0.475
3D body: height 0.25, standoff 0, extent -0.125,-0.125 0.125,0.125
3D body: height 0.25, standoff 0, extent -0.125,-0.475 0.125,-0.225
3D body: height 0.25, standoff 0, extent -0.428,1.1 -0.178,1.35
3D body: height 0.25, standoff 0, extent -0.428,0.4 -0.178,0.65
3D body: height 0.25, standoff 0, extent -0.428,0.75 -0.178,1
3D body: height 0.25, standoff 0, extent -0.428,0.05 -0.178,0.3
3D body: height 0.25, standoff 0, extent -0.428,-0.3 -0.178,-0.05
3D body: height 0.25, standoff 0, extent -0.731,0.575 -0.481,0.825
3D body: height 0.25, standoff 0, extent -0.731,0.925 -0.481,1.175
3D body: height 0.25, standoff 0, extent -0.731,1.275 -0.481,1.525
3D body: height 0.25, standoff 0, extent -0.731,0.225 -0.481,0.475
3D body: height 0.25, standoff 0, extent -0.731,-0.125 -0.481,0.125
3D body: height 0.25, standoff 0, extent -0.731,-0.475 -0.481,-0.225
3D body: height 0.25, standoff 0, extent -1.025,-0.628 -0.775,-0.378
3D body: height 0.25, standoff 0, extent -1.034,0.4 -0.784,0.65
3D body: height 0.25, standoff 0, extent -1.034,0.05 -0.784,0.3
3D body: height 0.25, standoff 0, extent -1.034,-0.3 -0.784,-0.05
3D body: height 0.25, standoff 0, extent -1.337,0.575 -1.087,0.825
3D body: height 0.25, standoff 0, extent -1.337,0.225 -1.087,0.475
3D body: height 0.25, standoff 0, extent -1.337,-0.125 -1.087,0.125
3D body: height 0.25, standoff 0, extent -1.337,-0.475 -1.087,-0.225
3D body: height 0.25, standoff 0, extent -1.64,0.75 -1.39,1
3D body: height 0.25, standoff 0, extent -1.64,0.4 -1.39,0.65
3D body: height 0.25, standoff 0, extent -1.64,0.05 -1.39,0.3
3D body: height 0.25, standoff 0, extent -1.64,-0.3 -1.39,-0.05
3D body: height 0.25, standoff 0, extent -1.64,-0.65 -1.39,-0.4
3D body: height 0.5, standoff 0.49, extent -1.816,1.468 -1.616,1.668
3D body: height 0.25, standoff 0, extent -0.428,-0.65 -0.178,-0.4
3D body: height 0.25, standoff 0, extent -0.125,-0.825 0.125,-0.575
3D body: height 0.25, standoff 0, extent -1.337,-0.825 -1.087,-0.575
3D body: height 0.25, standoff 0, extent -0.731,-0.825 -0.481,-0.575
3D body: height 0.25, standoff 0, extent -1.64,-1 -1.39,-0.75
3D body: height 0.25, standoff 0, extent -1.034,-1 -0.784,-0.75
3D body: height 0.25, standoff 0, extent -0.428,-1 -0.178,-0.75
3D body: height 0.25, standoff 0, extent -0.125,-1.175 0.125,-0.925
3D body: height 0.25, standoff 0, extent -1.337,-1.175 -1.087,-0.925
3D body: height 0.25, standoff 0, extent -0.731,-1.175 -0.481,-0.925
3D body: height 0.25, standoff 0, extent -1.64,-1.35 -1.39,-1.1
3D body: height 0.25, standoff 0, extent -1.034,-1.35 -0.784,-1.1
3D body: height 0.25, standoff 0, extent -0.428,-1.35 -0.178,-1.1
3D body: height 0.25, standoff 0, extent -0.125,-1.525 0.125,-1.275
3D body: height 0.25, standoff 0, extent -1.337,-1.525 -1.087,-1.275
3D body: height 0.25, standoff 0, extent -0.731,-1.525 -0.481,-1.275
3D body: height 0.49, standoff 0.16, extent -1.905,-1.742 1.905,1.744

## ICC_WLCSP100_4P40X4P38_P040 [mm] "MCD-01678"
height 0.59
pads (100):
  round 0.225 smd paste+0.012 mask+0.038: A1(-1.8,1.8) A2(-1.4,1.8) A3(-1,1.8) A4(-0.6,1.8) A5(-0.2,1.8) A6(0.2,1.8) A7(0.6,1.8) A8(1,1.8) A9(1.4,1.8) A10(1.8,1.8) B1(-1.8,1.4) B2(-1.4,1.4) B3(-1,1.4) B4(-0.6,1.4) B5(-0.2,1.4) B6(0.2,1.4) B7(0.6,1.4) B8(1,1.4) B9(1.4,1.4) B10(1.8,1.4) C1(-1.8,1) C2(-1.4,1) C3(-1,1) C4(-0.6,1) C5(-0.2,1) C6(0.2,1) C7(0.6,1) C8(1,1) C9(1.4,1) C10(1.8,1) D1(-1.8,0.6) D2(-1.4,0.6) D3(-1,0.6) D4(-0.6,0.6) D5(-0.2,0.6) D6(0.2,0.6) D7(0.6,0.6) D8(1,0.6) D9(1.4,0.6) D10(1.8,0.6) E1(-1.8,0.2) E2(-1.4,0.2) E3(-1,0.2) E4(-0.6,0.2) E5(-0.2,0.2) E6(0.2,0.2) E7(0.6,0.2) E8(1,0.2) E9(1.4,0.2) E10(1.8,0.2) F1(-1.8,-0.2) F2(-1.4,-0.2) F3(-1,-0.2) F4(-0.6,-0.2) F5(-0.2,-0.2) F6(0.2,-0.2) F7(0.6,-0.2) F8(1,-0.2) F9(1.4,-0.2) F10(1.8,-0.2) G1(-1.8,-0.6) G2(-1.4,-0.6) G3(-1,-0.6) G4(-0.6,-0.6) G5(-0.2,-0.6) G6(0.2,-0.6) G7(0.6,-0.6) G8(1,-0.6) G9(1.4,-0.6) G10(1.8,-0.6) H1(-1.8,-1) H2(-1.4,-1) H3(-1,-1) H4(-0.6,-1) H5(-0.2,-1) H6(0.2,-1) H7(0.6,-1) H8(1,-1) H9(1.4,-1) H10(1.8,-1) J1(-1.8,-1.4) J2(-1.4,-1.4) J3(-1,-1.4) J4(-0.6,-1.4) J5(-0.2,-1.4) J6(0.2,-1.4) J7(0.6,-1.4) J8(1,-1.4) J9(1.4,-1.4) J10(1.8,-1.4) K1(-1.8,-1.8) K2(-1.4,-1.8) K3(-1,-1.8) K4(-0.6,-1.8) K5(-0.2,-1.8) K6(0.2,-1.8) K7(0.6,-1.8) K8(1,-1.8) K9(1.4,-1.8) K10(1.8,-1.8)
Top Overlay:
  lines w0.12: -2.28,1.71 -2.28,2.27 -1.72,2.27 ; -2.13,-2.28 -2.13,2.12 2.29,2.12 2.29,-2.28 -2.13,-2.28
M14-Top Assembly:
  circle w0.01: c1.8,-0.2 r0.14
  circle w0.01: c1.4,-0.2 r0.14
  circle w0.01: c1,-0.2 r0.14
  circle w0.01: c0.6,-0.2 r0.14
  circle w0.01: c0.2,-0.2 r0.14
  circle w0.01: c-0.2,-0.2 r0.14
  circle w0.01: c-0.6,-0.2 r0.14
  circle w0.01: c-1,-0.2 r0.14
  circle w0.01: c-1.4,-0.2 r0.14
  circle w0.01: c-1.8,-0.2 r0.14
  circle w0.01: c-1.8,-0.6 r0.14
  circle w0.01: c-1.4,-0.6 r0.14
  circle w0.01: c-1,-0.6 r0.14
  circle w0.01: c-0.6,-0.6 r0.14
  circle w0.01: c-0.2,-0.6 r0.14
  circle w0.01: c0.2,-0.6 r0.14
  circle w0.01: c0.6,-0.6 r0.14
  circle w0.01: c1,-0.6 r0.14
  circle w0.01: c1.4,-0.6 r0.14
  circle w0.01: c1.8,-0.6 r0.14
  circle w0.01: c-1.8,-1 r0.14
  circle w0.01: c-1.4,-1 r0.14
  circle w0.01: c-1,-1 r0.14
  circle w0.01: c-0.6,-1 r0.14
  circle w0.01: c-0.2,-1 r0.14
  circle w0.01: c0.2,-1 r0.14
  circle w0.01: c0.6,-1 r0.14
  circle w0.01: c1,-1 r0.14
  circle w0.01: c1.4,-1 r0.14
  circle w0.01: c1.8,-1 r0.14
  circle w0.01: c-1.8,-1.4 r0.14
  circle w0.01: c-1.4,-1.4 r0.14
  circle w0.01: c-1,-1.4 r0.14
  circle w0.01: c-0.6,-1.4 r0.14
  circle w0.01: c-0.2,-1.4 r0.14
  circle w0.01: c0.2,-1.4 r0.14
  circle w0.01: c0.6,-1.4 r0.14
  circle w0.01: c1,-1.4 r0.14
  circle w0.01: c1.4,-1.4 r0.14
  circle w0.01: c1.8,-1.4 r0.14
  circle w0.01: c-1.8,-1.8 r0.14
  circle w0.01: c-1.4,-1.8 r0.14
  circle w0.01: c-1,-1.8 r0.14
  circle w0.01: c-0.6,-1.8 r0.14
  circle w0.01: c-0.2,-1.8 r0.14
  circle w0.01: c0.2,-1.8 r0.14
  circle w0.01: c0.6,-1.8 r0.14
  circle w0.01: c1,-1.8 r0.14
  circle w0.01: c1.4,-1.8 r0.14
  circle w0.01: c1.8,-1.8 r0.14
  circle w0.01: c1.8,0.2 r0.14
  circle w0.01: c1.4,0.2 r0.14
  circle w0.01: c1,0.2 r0.14
  circle w0.01: c0.6,0.2 r0.14
  circle w0.01: c0.2,0.2 r0.14
  circle w0.01: c-0.2,0.2 r0.14
  circle w0.01: c-0.6,0.2 r0.14
  circle w0.01: c-1,0.2 r0.14
  circle w0.01: c-1.4,0.2 r0.14
  circle w0.01: c-1.8,0.2 r0.14
  circle w0.01: c1.8,0.6 r0.14
  circle w0.01: c1.4,0.6 r0.14
  circle w0.01: c1,0.6 r0.14
  circle w0.01: c0.6,0.6 r0.14
  circle w0.01: c0.2,0.6 r0.14
  circle w0.01: c-0.2,0.6 r0.14
  circle w0.01: c-0.6,0.6 r0.14
  circle w0.01: c-1,0.6 r0.14
  circle w0.01: c-1.4,0.6 r0.14
  circle w0.01: c-1.8,0.6 r0.14
  circle w0.01: c1.8,1 r0.14
  circle w0.01: c1.4,1 r0.14
  circle w0.01: c1,1 r0.14
  circle w0.01: c0.6,1 r0.14
  circle w0.01: c0.2,1 r0.14
  circle w0.01: c-0.2,1 r0.14
  circle w0.01: c-0.6,1 r0.14
  circle w0.01: c-1,1 r0.14
  circle w0.01: c-1.4,1 r0.14
  circle w0.01: c-1.8,1 r0.14
  circle w0.01: c1.8,1.4 r0.14
  circle w0.01: c1.4,1.4 r0.14
  circle w0.01: c1,1.4 r0.14
  circle w0.01: c0.6,1.4 r0.14
  circle w0.01: c0.2,1.4 r0.14
  circle w0.01: c-0.2,1.4 r0.14
  circle w0.01: c-0.6,1.4 r0.14
  circle w0.01: c-1,1.4 r0.14
  circle w0.01: c-1.4,1.4 r0.14
  circle w0.01: c-1.8,1.4 r0.14
  circle w0.01: c-1.8,1.8 r0.14
  circle w0.01: c-1.4,1.8 r0.14
  circle w0.01: c-1,1.8 r0.14
  circle w0.01: c-0.6,1.8 r0.14
  circle w0.01: c-0.2,1.8 r0.14
  circle w0.01: c0.2,1.8 r0.14
  circle w0.01: c0.6,1.8 r0.14
  circle w0.01: c1,1.8 r0.14
  circle w0.01: c1.4,1.8 r0.14
  circle w0.01: c1.8,1.8 r0.14
  lines w0.01: -2.13,-2.28 -2.13,2.12 2.29,2.12 2.29,-2.28 -2.13,-2.28
  text "K1" at -2.045,-1.955 h0.5
  text "A10" at 1.455,1.645 h0.5
  text "A1" at -2.045,1.645 h0.5
  text "'.Designator'" at -1.92,-0.58 h0.75
M16-Top Courtyard:
  lines w0.01: -2.38,-2.53 2.54,-2.53 2.54,2.37 -2.38,2.37 -2.38,-2.53
3D body: height 0.26, standoff -0.02, extent 1.669,-0.338 1.94,-0.062
3D body: height 0.26, standoff -0.02, extent 1.269,-0.338 1.54,-0.062
3D body: height 0.26, standoff -0.02, extent 0.869,-0.338 1.14,-0.062
3D body: height 0.26, standoff -0.02, extent 0.469,-0.338 0.74,-0.062
3D body: height 0.26, standoff -0.02, extent 0.069,-0.338 0.34,-0.062
3D body: height 0.26, standoff -0.02, extent -0.331,-0.338 -0.06,-0.062
3D body: height 0.26, standoff -0.02, extent -0.731,-0.338 -0.46,-0.062
3D body: height 0.26, standoff -0.02, extent -1.131,-0.338 -0.86,-0.062
3D body: height 0.26, standoff -0.02, extent -1.531,-0.338 -1.26,-0.062
3D body: height 0.26, standoff -0.02, extent -1.931,-0.338 -1.66,-0.062
3D body: height 0.26, standoff -0.02, extent -1.931,-0.738 -1.66,-0.462
3D body: height 0.26, standoff -0.02, extent -1.531,-0.738 -1.26,-0.462
3D body: height 0.26, standoff -0.02, extent -1.131,-0.738 -0.86,-0.462
3D body: height 0.26, standoff -0.02, extent -0.731,-0.738 -0.46,-0.462
3D body: height 0.26, standoff -0.02, extent -0.331,-0.738 -0.06,-0.462
3D body: height 0.26, standoff -0.02, extent 0.069,-0.738 0.34,-0.462
3D body: height 0.26, standoff -0.02, extent 0.469,-0.738 0.74,-0.462
3D body: height 0.26, standoff -0.02, extent 0.869,-0.738 1.14,-0.462
3D body: height 0.26, standoff -0.02, extent 1.269,-0.738 1.54,-0.462
3D body: height 0.26, standoff -0.02, extent 1.669,-0.738 1.94,-0.462
3D body: height 0.26, standoff -0.02, extent -1.931,-1.138 -1.66,-0.862
3D body: height 0.26, standoff -0.02, extent -1.531,-1.138 -1.26,-0.862
3D body: height 0.26, standoff -0.02, extent -1.131,-1.138 -0.86,-0.862
3D body: height 0.26, standoff -0.02, extent -0.731,-1.138 -0.46,-0.862
3D body: height 0.26, standoff -0.02, extent -0.331,-1.138 -0.06,-0.862
3D body: height 0.26, standoff -0.02, extent 0.069,-1.138 0.34,-0.862
3D body: height 0.26, standoff -0.02, extent 0.469,-1.138 0.74,-0.862
3D body: height 0.26, standoff -0.02, extent 0.869,-1.138 1.14,-0.862
3D body: height 0.26, standoff -0.02, extent 1.269,-1.138 1.54,-0.862
3D body: height 0.26, standoff -0.02, extent 1.669,-1.138 1.94,-0.862
3D body: height 0.26, standoff -0.02, extent -1.931,-1.538 -1.66,-1.262
3D body: height 0.26, standoff -0.02, extent -1.531,-1.538 -1.26,-1.262
3D body: height 0.26, standoff -0.02, extent -1.131,-1.538 -0.86,-1.262
3D body: height 0.26, standoff -0.02, extent -0.731,-1.538 -0.46,-1.262
3D body: height 0.26, standoff -0.02, extent -0.331,-1.538 -0.06,-1.262
3D body: height 0.26, standoff -0.02, extent 0.069,-1.538 0.34,-1.262
3D body: height 0.26, standoff -0.02, extent 0.469,-1.538 0.74,-1.262
3D body: height 0.26, standoff -0.02, extent 0.869,-1.538 1.14,-1.262
3D body: height 0.26, standoff -0.02, extent 1.269,-1.538 1.54,-1.262
3D body: height 0.26, standoff -0.02, extent 1.669,-1.538 1.94,-1.262
3D body: height 0.26, standoff -0.02, extent -1.931,-1.938 -1.66,-1.662
3D body: height 0.26, standoff -0.02, extent -1.531,-1.938 -1.26,-1.662
3D body: height 0.26, standoff -0.02, extent -1.131,-1.938 -0.86,-1.662
3D body: height 0.26, standoff -0.02, extent -0.731,-1.938 -0.46,-1.662
3D body: height 0.26, standoff -0.02, extent -0.331,-1.938 -0.06,-1.662
3D body: height 0.26, standoff -0.02, extent 0.069,-1.938 0.34,-1.662
3D body: height 0.26, standoff -0.02, extent 0.469,-1.938 0.74,-1.662
3D body: height 0.26, standoff -0.02, extent 0.869,-1.938 1.14,-1.662
3D body: height 0.26, standoff -0.02, extent 1.269,-1.938 1.54,-1.662
3D body: height 0.26, standoff -0.02, extent 1.669,-1.938 1.94,-1.662
3D body: height 0.26, standoff -0.02, extent 1.669,0.062 1.94,0.338
3D body: height 0.26, standoff -0.02, extent 1.269,0.062 1.54,0.338
3D body: height 0.26, standoff -0.02, extent 0.869,0.062 1.14,0.338
3D body: height 0.26, standoff -0.02, extent 0.469,0.062 0.74,0.338
3D body: height 0.26, standoff -0.02, extent 0.069,0.062 0.34,0.338
3D body: height 0.26, standoff -0.02, extent -0.331,0.062 -0.06,0.338
3D body: height 0.26, standoff -0.02, extent -0.731,0.062 -0.46,0.338
3D body: height 0.26, standoff -0.02, extent -1.131,0.062 -0.86,0.338
3D body: height 0.26, standoff -0.02, extent -1.531,0.062 -1.26,0.338
3D body: height 0.26, standoff -0.02, extent -1.931,0.062 -1.66,0.338
3D body: height 0.26, standoff -0.02, extent 1.669,0.462 1.94,0.738
3D body: height 0.26, standoff -0.02, extent 1.269,0.462 1.54,0.738
3D body: height 0.26, standoff -0.02, extent 0.869,0.462 1.14,0.738
3D body: height 0.26, standoff -0.02, extent 0.469,0.462 0.74,0.738
3D body: height 0.26, standoff -0.02, extent 0.069,0.462 0.34,0.738
3D body: height 0.26, standoff -0.02, extent -0.331,0.462 -0.06,0.738
3D body: height 0.26, standoff -0.02, extent -0.731,0.462 -0.46,0.738
3D body: height 0.26, standoff -0.02, extent -1.131,0.462 -0.86,0.738
3D body: height 0.26, standoff -0.02, extent -1.531,0.462 -1.26,0.738
3D body: height 0.26, standoff -0.02, extent -1.931,0.462 -1.66,0.738
3D body: height 0.26, standoff -0.02, extent 1.669,0.862 1.94,1.138
3D body: height 0.26, standoff -0.02, extent 1.269,0.862 1.54,1.138
3D body: height 0.26, standoff -0.02, extent 0.869,0.862 1.14,1.138
3D body: height 0.26, standoff -0.02, extent 0.469,0.862 0.74,1.138
3D body: height 0.26, standoff -0.02, extent 0.069,0.862 0.34,1.138
3D body: height 0.26, standoff -0.02, extent -0.331,0.862 -0.06,1.138
3D body: height 0.26, standoff -0.02, extent -0.731,0.862 -0.46,1.138
3D body: height 0.26, standoff -0.02, extent -1.131,0.862 -0.86,1.138
3D body: height 0.26, standoff -0.02, extent -1.531,0.862 -1.26,1.138
3D body: height 0.26, standoff -0.02, extent -1.931,0.862 -1.66,1.138
3D body: height 0.26, standoff -0.02, extent 1.669,1.262 1.94,1.538
3D body: height 0.26, standoff -0.02, extent 1.269,1.262 1.54,1.538
3D body: height 0.26, standoff -0.02, extent 0.869,1.262 1.14,1.538
3D body: height 0.26, standoff -0.02, extent 0.469,1.262 0.74,1.538
3D body: height 0.26, standoff -0.02, extent 0.069,1.262 0.34,1.538
3D body: height 0.26, standoff -0.02, extent -0.331,1.262 -0.06,1.538
3D body: height 0.26, standoff -0.02, extent -0.731,1.262 -0.46,1.538
3D body: height 0.26, standoff -0.02, extent -1.131,1.262 -0.86,1.538
3D body: height 0.26, standoff -0.02, extent -1.531,1.262 -1.26,1.538
3D body: height 0.26, standoff -0.02, extent -1.931,1.262 -1.66,1.538
3D body: height 0.26, standoff -0.02, extent -1.931,1.662 -1.66,1.938
3D body: height 0.59, standoff 0.22, extent -2.13,-2.28 2.29,2.12
3D body: height 0.6, standoff 0.59, extent -1.949,1.65 -1.65,1.95
3D body: height 0.26, standoff -0.02, extent -1.531,1.662 -1.26,1.938
3D body: height 0.26, standoff -0.02, extent -1.131,1.662 -0.86,1.938
3D body: height 0.26, standoff -0.02, extent -0.731,1.662 -0.46,1.938
3D body: height 0.26, standoff -0.02, extent -0.331,1.662 -0.06,1.938
3D body: height 0.26, standoff -0.02, extent 0.069,1.662 0.34,1.938
3D body: height 0.26, standoff -0.02, extent 0.469,1.662 0.74,1.938
3D body: height 0.26, standoff -0.02, extent 0.869,1.662 1.14,1.938
3D body: height 0.26, standoff -0.02, extent 1.269,1.662 1.54,1.938
3D body: height 0.26, standoff -0.02, extent 1.669,1.662 1.94,1.938

## ICC_WLP4_0P85x0P85_P040 [mm] "MCD-02453"
height 0.6
pads (4):
  round 0.2 smd mask+0.05: A1(-0.2,0.2) A2(0.2,0.2) B1(-0.2,-0.2) B2(0.2,-0.2)
Top Overlay:
  circle w0.12: c-0.38,0.38 r0.025
M14-Top Assembly:
  circle w0.01: c0.2,-0.2 r0.125
  circle w0.01: c-0.2,-0.2 r0.125
  circle w0.01: c-0.2,0.2 r0.125
  circle w0.01: c0.2,0.2 r0.125
  lines w0.01: -0.44,0.35 -0.35,0.44 ; -0.44,-0.44 0.44,-0.44 0.44,0.44 -0.44,0.44 -0.44,-0.44
  text "A1" at -0.315,0.135 h0.2
  text "'.Designator'" at -2,-0.5 h0.75
M16-Top Courtyard:
  lines w0.01: -0.49,-0.49 0.49,-0.49 0.49,0.49 -0.49,0.49 -0.49,-0.49
3D body: height 0.24, standoff -0.02, extent -0.317,0.077 -0.075,0.323
3D body: height 0.24, standoff -0.02, extent 0.083,0.077 0.325,0.323
3D body: height 0.24, standoff -0.02, extent -0.317,-0.323 -0.075,-0.077
3D body: height 0.24, standoff -0.02, extent 0.083,-0.323 0.325,-0.077
3D body: height 0.6, standoff 0.14, extent -0.44,-0.44 0.44,0.44
3D body "User Library-WLP-4.STEP": height 0.34, standoff -0.01, extent -0.422,-0.422 0.423,0.423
